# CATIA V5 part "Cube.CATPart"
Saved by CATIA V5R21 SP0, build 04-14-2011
Part number: Part1
Bounding box of the stored display mesh (mm): x -1093.5 to 1093.5, y -1093.5 to 1093.5, z -1093.5 to 1093.5
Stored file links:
  C:\Users\Dario\Google Drive\CATIA VBA\codingChallenge\02_MenguerSpongeFractal\Cube.CATPart
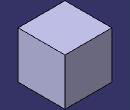
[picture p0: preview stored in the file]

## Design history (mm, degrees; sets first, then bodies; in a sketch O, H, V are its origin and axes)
Parameters
  cubeSize = 2187 mm
Body1 (main body)
  Sketch1 on zx-plane, origin (0, 0, 0), H (-1, 0, 0), V (0, 0, 1)
    line L1 (1093.5, 1093.5) -> (1093.5, -1093.5)
    line L2 (1093.5, -1093.5) -> (-1093.5, -1093.5)
    line L3 (-1093.5, -1093.5) -> (-1093.5, 1093.5)
    line L4 (-1093.5, 1093.5) -> (1093.5, 1093.5)
    axis line L5 (0, 0) -> (1093.5, -1093.5)
    angle L5 H = 45
    length L2 = 2187 {= cubeSize}
    vertical: L1 V, L3 V
    horizontal: L2 H, L4 H
    equidistance: L1 L3 O, L2 L4 O
  Sketch2 on yz-plane, origin (0, 0, 0), H (0, 1, 0), V (0, 0, 1)
    line L1 (1093.5, 1093.5) -> (1093.5, -1093.5)
    line L2 (1093.5, -1093.5) -> (-1093.5, -1093.5)
    line L3 (-1093.5, -1093.5) -> (-1093.5, 1093.5)
    line L4 (-1093.5, 1093.5) -> (1093.5, 1093.5)
    axis line L5 (0, 0) -> (1093.5, -1093.5)
    angle L5 H = 45
    length L2 = 2187 {= cubeSize}
    vertical: L1 V, L3 V
    horizontal: L2 H, L4 H
    equidistance: L1 L3 O, L2 L4 O
  SolidCombine1: FirstComponentDirection Sketch1, FirstComponentProfile Sketch1, SecondComponentDirection Sketch2, SecondComponentProfile Sketch2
